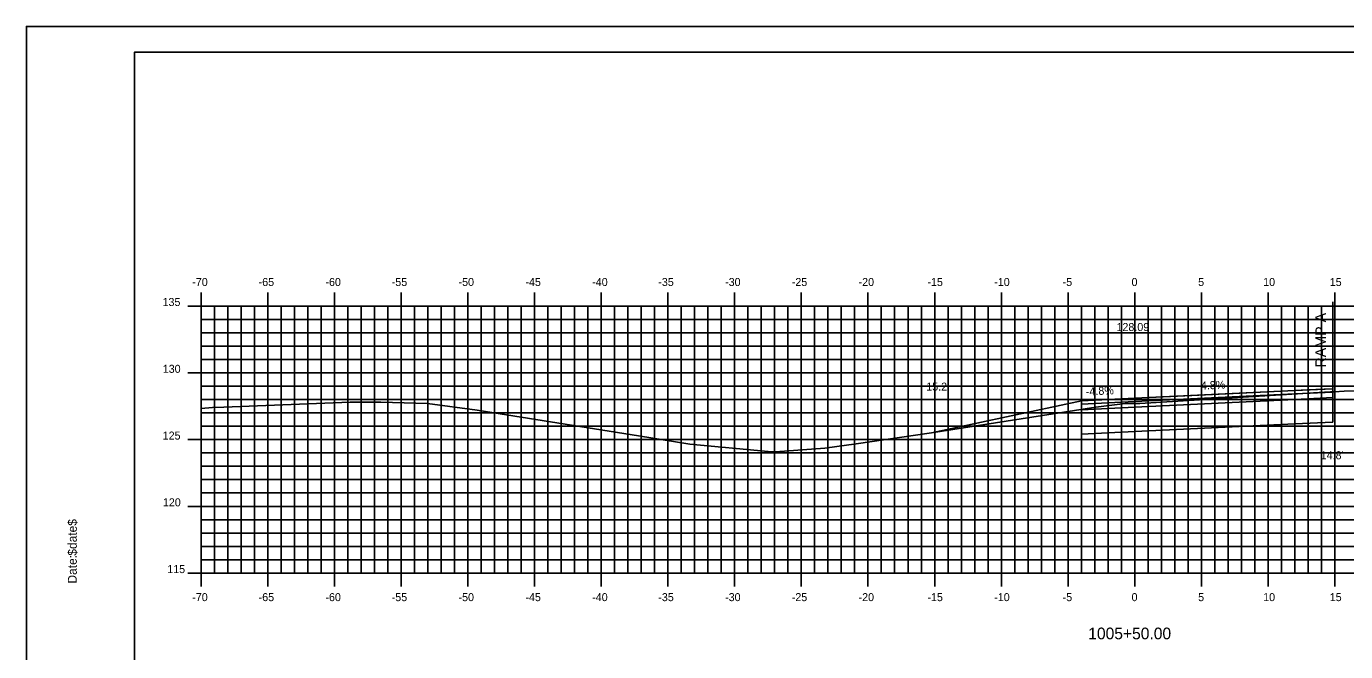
# Model space of a CAD drawing. Extents: x 851295 to 851467, y 365624 to 365734.
# Drawn here: x 851294.9 to 851393.8, y 365687.1 to 365734 of the extents above; entities that cross this region are included whole.
import ezdxf

# ---------------------------------------------------------------- set-up
doc = ezdxf.new("R2010")
doc.units = 0
for name, color, linetype in [('ANNOTATION', 7, 'Continuous'), ('BORDER', 7, 'Continuous'), ('D_Roadway_Centerline', 7, 'Continuous'), ('D_Roadway_Centerline_Text', 7, 'Continuous'), ('D_Roadway_Edge_Shoulder', 7, 'Continuous'), ('D_Roadway_Edge_TW', 7, 'Continuous'), ('D_Roadway_FinishedGrade', 7, 'Continuous'), ('D_Roadway_Pavement', 7, 'Continuous'), ('D_Roadway_SubGrade', 7, 'Continuous'), ('D_Text_Standard', 7, 'Continuous'), ('H_V ANNOTATION', 7, 'Continuous'), ('M_Roadway_Centerline', 7, 'Continuous'), ('MAJOR', 7, 'Continuous'), ('MINOR', 7, 'Continuous'), ('PLOT BOUNDARY', 7, 'Continuous'), ('S_Roadway_Centerline', 7, 'Continuous')]:
    doc.layers.add(name, color=color, linetype=linetype)

msp = doc.modelspace()

# ---------------------------------------------------------------- linework, layer by layer
at = {"layer": 'BORDER'}
msp.add_lwpolyline([(851303.009, 365627.027), (851463.009, 365627.027), (851463.009, 365732.027), (851303.009, 365732.027)], close=True, dxfattribs=at)
at = {"layer": 'D_Roadway_Centerline'}
msp.add_line((851374.009, 365705.93), (851362.77, 365703.526), dxfattribs=at)
msp.add_lwpolyline([(851374.009, 365705.93), (851374.009, 365705.93), (851376.068, 365706.029), (851378.009, 365706.122), (851378.011, 365706.122), (851382.296, 365706.328), (851390.009, 365706.698), (851390.928, 365706.742), (851392.853, 365706.835), (851392.855, 365706.835)], dxfattribs=at)
at = {"layer": 'D_Roadway_Edge_Shoulder'}
msp.add_lwpolyline([(851378.009, 365706.122), (851374.009, 365705.93), (851374.009, 365705.68), (851378.009, 365705.872)], close=True, dxfattribs=at)
at = {"layer": 'D_Roadway_Edge_TW'}
for points in [[(851390.009, 365706.698), (851392.855, 365706.835), (851392.855, 365706.585), (851390.009, 365706.448)], [(851378.009, 365706.122), (851390.009, 365706.698), (851390.009, 365706.448), (851378.009, 365705.872)]]:
    msp.add_lwpolyline(points, close=True, dxfattribs=at)
at = {"layer": 'D_Roadway_FinishedGrade'}
for p, q in [((851392.855, 365706.835), (851392.855, 365706.585)), ((851374.009, 365705.93), (851374.009, 365705.68)), ((851378.009, 365706.122), (851378.009, 365705.872)), ((851390.009, 365706.698), (851390.009, 365706.448))]:
    msp.add_line(p, q, dxfattribs=at)
at = {"layer": 'D_Roadway_Pavement'}
for points in [[(851378.009, 365705.872), (851374.009, 365705.68), (851374.009, 365705.263), (851378.009, 365705.455)], [(851378.009, 365705.872), (851390.009, 365706.448), (851390.009, 365706.031), (851378.009, 365705.455)], [(851390.009, 365706.448), (851392.855, 365706.585), (851392.855, 365706.168), (851390.009, 365706.031)]]:
    msp.add_lwpolyline(points, close=True, dxfattribs=at)
at = {"layer": 'D_Roadway_SubGrade'}
msp.add_line((851392.855, 365713.332), (851392.855, 365704.335), dxfattribs=at)
for points in [[(851378.009, 365705.455), (851374.009, 365705.263), (851374.009, 365705.763), (851374.009, 365705.93), (851374.009, 365703.43), (851378.009, 365703.622)], [(851378.009, 365705.455), (851390.009, 365706.031), (851390.009, 365704.198), (851378.009, 365703.622)], [(851390.009, 365706.031), (851392.855, 365706.168), (851392.855, 365704.335), (851390.009, 365704.198)]]:
    msp.add_lwpolyline(points, close=True, dxfattribs=at)
at = {"layer": 'MAJOR'}
for p, q in [((851308.009, 365714.029), (851308.009, 365713.027)), ((851313.009, 365714.029), (851313.009, 365713.027)), ((851318.009, 365714.029), (851318.009, 365713.027)), ((851323.009, 365714.029), (851323.009, 365713.027)), ((851328.009, 365714.029), (851328.009, 365713.027)), ((851333.009, 365714.029), (851333.009, 365713.027)), ((851338.009, 365714.029), (851338.009, 365713.027)), ((851343.009, 365714.029), (851343.009, 365713.027)), ((851348.009, 365714.029), (851348.009, 365713.027)), ((851353.009, 365714.029), (851353.009, 365713.027)), ((851358.009, 365714.029), (851358.009, 365713.027)), ((851363.009, 365714.029), (851363.009, 365713.027)), ((851368.009, 365714.029), (851368.009, 365713.027)), ((851373.009, 365714.029), (851373.009, 365713.027)), ((851378.009, 365714.029), (851378.009, 365713.027)), ((851383.009, 365714.029), (851383.009, 365713.027)), ((851388.009, 365714.029), (851388.009, 365713.027)), ((851393.009, 365714.029), (851393.009, 365713.027)), ((851307.007, 365713.027), (851308.009, 365713.027)), ((851308.009, 365713.027), (851448.009, 365713.027)), ((851308.009, 365693.027), (851308.009, 365713.027)), ((851308.009, 365693.027), (851308.009, 365713.027)), ((851308.009, 365713.027), (851448.009, 365713.027)), ((851313.009, 365693.027), (851313.009, 365713.027)), ((851318.009, 365693.027), (851318.009, 365713.027)), ((851323.009, 365693.027), (851323.009, 365713.027)), ((851328.009, 365693.027), (851328.009, 365713.027)), ((851333.009, 365693.027), (851333.009, 365713.027)), ((851338.009, 365693.027), (851338.009, 365713.027)), ((851343.009, 365693.027), (851343.009, 365713.027)), ((851348.009, 365693.027), (851348.009, 365713.027)), ((851353.009, 365693.027), (851353.009, 365713.027)), ((851358.009, 365693.027), (851358.009, 365713.027)), ((851363.009, 365693.027), (851363.009, 365713.027)), ((851368.009, 365693.027), (851368.009, 365713.027)), ((851373.009, 365693.027), (851373.009, 365713.027)), ((851378.009, 365693.027), (851378.009, 365713.027)), ((851383.009, 365693.027), (851383.009, 365713.027)), ((851388.009, 365693.027), (851388.009, 365713.027)), ((851393.009, 365693.027), (851393.009, 365713.027)), ((851307.007, 365708.027), (851308.009, 365708.027)), ((851308.009, 365708.027), (851448.009, 365708.027)), ((851307.007, 365703.027), (851308.009, 365703.027)), ((851308.009, 365703.027), (851448.009, 365703.027)), ((851307.007, 365698.027), (851308.009, 365698.027)), ((851308.009, 365698.027), (851448.009, 365698.027)), ((851307.007, 365693.027), (851308.009, 365693.027)), ((851308.009, 365693.027), (851448.009, 365693.027)), ((851308.009, 365693.027), (851448.009, 365693.027)), ((851308.009, 365692.025), (851308.009, 365693.027)), ((851313.009, 365692.025), (851313.009, 365693.027)), ((851318.009, 365692.025), (851318.009, 365693.027)), ((851323.009, 365692.025), (851323.009, 365693.027)), ((851328.009, 365692.025), (851328.009, 365693.027)), ((851333.009, 365692.025), (851333.009, 365693.027)), ((851338.009, 365692.025), (851338.009, 365693.027)), ((851343.009, 365692.025), (851343.009, 365693.027)), ((851348.009, 365692.025), (851348.009, 365693.027)), ((851353.009, 365692.025), (851353.009, 365693.027)), ((851358.009, 365692.025), (851358.009, 365693.027)), ((851363.009, 365692.025), (851363.009, 365693.027)), ((851368.009, 365692.025), (851368.009, 365693.027)), ((851373.009, 365692.025), (851373.009, 365693.027)), ((851378.009, 365692.025), (851378.009, 365693.027)), ((851383.009, 365692.025), (851383.009, 365693.027)), ((851388.009, 365692.025), (851388.009, 365693.027)), ((851393.009, 365692.025), (851393.009, 365693.027))]:
    msp.add_line(p, q, dxfattribs=at)
at = {"layer": 'MINOR'}
for p, q in [((851309.009, 365693.027), (851309.009, 365713.027)), ((851310.009, 365693.027), (851310.009, 365713.027)), ((851311.009, 365693.027), (851311.009, 365713.027)), ((851312.009, 365693.027), (851312.009, 365713.027)), ((851314.009, 365693.027), (851314.009, 365713.027)), ((851315.009, 365693.027), (851315.009, 365713.027)), ((851316.009, 365693.027), (851316.009, 365713.027)), ((851317.009, 365693.027), (851317.009, 365713.027)), ((851319.009, 365693.027), (851319.009, 365713.027)), ((851320.009, 365693.027), (851320.009, 365713.027)), ((851321.009, 365693.027), (851321.009, 365713.027)), ((851322.009, 365693.027), (851322.009, 365713.027)), ((851324.009, 365693.027), (851324.009, 365713.027)), ((851325.009, 365693.027), (851325.009, 365713.027)), ((851326.009, 365693.027), (851326.009, 365713.027)), ((851327.009, 365693.027), (851327.009, 365713.027)), ((851329.009, 365693.027), (851329.009, 365713.027)), ((851330.009, 365693.027), (851330.009, 365713.027)), ((851331.009, 365693.027), (851331.009, 365713.027)), ((851332.009, 365693.027), (851332.009, 365713.027)), ((851334.009, 365693.027), (851334.009, 365713.027)), ((851335.009, 365693.027), (851335.009, 365713.027)), ((851336.009, 365693.027), (851336.009, 365713.027)), ((851337.009, 365693.027), (851337.009, 365713.027)), ((851339.009, 365693.027), (851339.009, 365713.027)), ((851340.009, 365693.027), (851340.009, 365713.027)), ((851341.009, 365693.027), (851341.009, 365713.027)), ((851342.009, 365693.027), (851342.009, 365713.027)), ((851344.009, 365693.027), (851344.009, 365713.027)), ((851345.009, 365693.027), (851345.009, 365713.027)), ((851346.009, 365693.027), (851346.009, 365713.027)), ((851347.009, 365693.027), (851347.009, 365713.027)), ((851349.009, 365693.027), (851349.009, 365713.027)), ((851350.009, 365693.027), (851350.009, 365713.027)), ((851351.009, 365693.027), (851351.009, 365713.027)), ((851352.009, 365693.027), (851352.009, 365713.027)), ((851354.009, 365693.027), (851354.009, 365713.027)), ((851355.009, 365693.027), (851355.009, 365713.027)), ((851356.009, 365693.027), (851356.009, 365713.027)), ((851357.009, 365693.027), (851357.009, 365713.027)), ((851359.009, 365693.027), (851359.009, 365713.027)), ((851360.009, 365693.027), (851360.009, 365713.027)), ((851361.009, 365693.027), (851361.009, 365713.027)), ((851362.009, 365693.027), (851362.009, 365713.027)), ((851364.009, 365693.027), (851364.009, 365713.027)), ((851365.009, 365693.027), (851365.009, 365713.027)), ((851366.009, 365693.027), (851366.009, 365713.027)), ((851367.009, 365693.027), (851367.009, 365713.027)), ((851369.009, 365693.027), (851369.009, 365713.027)), ((851370.009, 365693.027), (851370.009, 365713.027)), ((851371.009, 365693.027), (851371.009, 365713.027)), ((851372.009, 365693.027), (851372.009, 365713.027)), ((851374.009, 365693.027), (851374.009, 365713.027)), ((851375.009, 365693.027), (851375.009, 365713.027)), ((851376.009, 365693.027), (851376.009, 365713.027)), ((851377.009, 365693.027), (851377.009, 365713.027)), ((851379.009, 365693.027), (851379.009, 365713.027)), ((851380.009, 365693.027), (851380.009, 365713.027)), ((851381.009, 365693.027), (851381.009, 365713.027)), ((851382.009, 365693.027), (851382.009, 365713.027)), ((851384.009, 365693.027), (851384.009, 365713.027)), ((851385.009, 365693.027), (851385.009, 365713.027)), ((851386.009, 365693.027), (851386.009, 365713.027)), ((851387.009, 365693.027), (851387.009, 365713.027)), ((851389.009, 365693.027), (851389.009, 365713.027)), ((851390.009, 365693.027), (851390.009, 365713.027)), ((851391.009, 365693.027), (851391.009, 365713.027)), ((851392.009, 365693.027), (851392.009, 365713.027)), ((851308.009, 365712.027), (851448.009, 365712.027)), ((851308.009, 365712.027), (851309.011, 365712.027)), ((851308.009, 365711.027), (851448.009, 365711.027)), ((851308.009, 365711.027), (851309.011, 365711.027)), ((851308.009, 365710.027), (851448.009, 365710.027)), ((851308.009, 365710.027), (851309.011, 365710.027)), ((851308.009, 365709.027), (851448.009, 365709.027)), ((851308.009, 365709.027), (851309.011, 365709.027)), ((851308.009, 365707.027), (851448.009, 365707.027)), ((851308.009, 365707.027), (851309.011, 365707.027)), ((851308.009, 365706.027), (851448.009, 365706.027)), ((851308.009, 365706.027), (851309.011, 365706.027)), ((851308.009, 365705.027), (851448.009, 365705.027)), ((851308.009, 365705.027), (851309.011, 365705.027)), ((851308.009, 365704.027), (851448.009, 365704.027)), ((851308.009, 365704.027), (851309.011, 365704.027)), ((851308.009, 365702.027), (851448.009, 365702.027)), ((851308.009, 365702.027), (851309.011, 365702.027)), ((851308.009, 365701.027), (851448.009, 365701.027)), ((851308.009, 365701.027), (851309.011, 365701.027)), ((851308.009, 365700.027), (851448.009, 365700.027)), ((851308.009, 365700.027), (851309.011, 365700.027)), ((851308.009, 365699.027), (851448.009, 365699.027)), ((851308.009, 365699.027), (851309.011, 365699.027)), ((851308.009, 365697.027), (851448.009, 365697.027)), ((851308.009, 365697.027), (851309.011, 365697.027)), ((851308.009, 365696.027), (851448.009, 365696.027)), ((851308.009, 365696.027), (851309.011, 365696.027)), ((851308.009, 365695.027), (851448.009, 365695.027)), ((851308.009, 365695.027), (851309.011, 365695.027)), ((851308.009, 365694.027), (851448.009, 365694.027)), ((851308.009, 365694.027), (851309.011, 365694.027))]:
    msp.add_line(p, q, dxfattribs=at)
at = {"layer": 'PLOT BOUNDARY'}
msp.add_lwpolyline([(851294.916, 365623.968), (851464.916, 365623.968), (851464.916, 365733.968), (851294.916, 365733.968)], close=True, dxfattribs=at)
at = {"layer": 'S_Roadway_Centerline'}
msp.add_lwpolyline([(851308.009, 365705.355), (851308.874, 365705.431), (851309.723, 365705.447), (851319.199, 365705.834), (851321.484, 365705.834), (851324.978, 365705.734), (851328.721, 365705.228), (851340.802, 365703.299), (851344.643, 365702.691), (851350.527, 365702.124), (851351.065, 365702.11), (851354.77, 365702.377), (851357.13, 365702.72), (851362.77, 365703.526), (851375.085, 365705.449), (851377.289, 365705.734), (851378.397, 365705.725), (851392.236, 365706.572), (851392.678, 365706.596), (851392.903, 365706.611), (851392.972, 365706.605), (851393.7, 365706.643), (851410.21, 365707.188)], dxfattribs=at)

# ---------------------------------------------------------------- texts
at = {"layer": 'ANNOTATION'}
for s, height, rotation, p in [('RAMP A', 0.8, 90, (851392.348, 365708.416)), ('-4.8%', 0.6, 2.74795, (851374.356, 365706.323)), ('4.8%', 0.6, 2.74806, (851382.979, 365706.761))]:
    msp.add_text(s, height=height, rotation=rotation, dxfattribs=at).set_placement(p)
at = {"layer": 'BORDER'}
for s, p in [('$date$', (851298.694, 365694.332)), ('Date:', (851298.694, 365692.244))]:
    msp.add_text(s, height=0.6696, rotation=90, dxfattribs=at).set_placement(p)
at = {"layer": 'D_Roadway_Centerline'}
for s, p in [('C', (851378.004, 365706.122)), ('L', (851378.009, 365706.114))]:
    msp.add_text(s, height=0.0146, dxfattribs=at).set_placement(p)
at = {"layer": 'D_Roadway_Centerline_Text'}
msp.add_text('128.09', height=0.6, dxfattribs=at).set_placement((851376.639, 365711.154))
at = {"layer": 'D_Text_Standard'}
for s, p in [("15.2'", (851362.379, 365706.693)), ("14.8'", (851391.948, 365701.553))]:
    msp.add_text(s, height=0.6, dxfattribs=at).set_placement(p)
at = {"layer": 'H_V ANNOTATION'}
for s, height, p in [('-70', 0.6, (851307.351, 365714.527)), ('-65', 0.6, (851312.327, 365714.527)), ('-60', 0.6, (851317.335, 365714.527)), ('-55', 0.6, (851322.305, 365714.527)), ('-50', 0.6, (851327.313, 365714.527)), ('-45', 0.6, (851332.327, 365714.527)), ('-40', 0.6, (851337.335, 365714.527)), ('-35', 0.6, (851342.289, 365714.527)), ('-30', 0.6, (851347.297, 365714.527)), ('-25', 0.6, (851352.295, 365714.527)), ('-20', 0.6, (851357.303, 365714.527)), ('-15', 0.6, (851362.466, 365714.527)), ('-10', 0.6, (851367.474, 365714.527)), ('-5', 0.6, (851372.6, 365714.527)), ('0', 0.6, (851377.768, 365714.527)), ('5', 0.6, (851382.76, 365714.527)), ('10', 0.6, (851387.634, 365714.527)), ('15', 0.6, (851392.626, 365714.527)), ('135', 0.6, (851305.123, 365713.027)), ('130', 0.6, (851305.139, 365708.027)), ('125', 0.6, (851305.134, 365703.027)), ('120', 0.6, (851305.15, 365698.027)), ('115', 0.6, (851305.476, 365693.027)), ('-70', 0.6, (851307.351, 365690.927)), ('-65', 0.6, (851312.327, 365690.927)), ('-60', 0.6, (851317.335, 365690.927)), ('-55', 0.6, (851322.305, 365690.927)), ('-50', 0.6, (851327.313, 365690.927)), ('-45', 0.6, (851332.327, 365690.927)), ('-40', 0.6, (851337.335, 365690.927)), ('-35', 0.6, (851342.289, 365690.927)), ('-30', 0.6, (851347.297, 365690.927)), ('-25', 0.6, (851352.295, 365690.927)), ('-20', 0.6, (851357.303, 365690.927)), ('-15', 0.6, (851362.466, 365690.927)), ('-10', 0.6, (851367.474, 365690.927)), ('-5', 0.6, (851372.6, 365690.927)), ('0', 0.6, (851377.768, 365690.927)), ('5', 0.6, (851382.76, 365690.927)), ('10', 0.6, (851387.634, 365690.927)), ('15', 0.6, (851392.626, 365690.927)), ('1005+50.00', 0.875, (851374.521, 365688.07))]:
    msp.add_text(s, height=height, dxfattribs=at).set_placement(p)
at = {"layer": 'M_Roadway_Centerline'}
for s, p in [('C', (851392.897, 365706.611)), ('L', (851392.903, 365706.604)), ('C', (851308.869, 365705.431)), ('L', (851308.874, 365705.424))]:
    msp.add_text(s, height=0.0146, dxfattribs=at).set_placement(p)
at = {"layer": 'MAJOR'}
msp.add_text('-', height=0.006, dxfattribs=at).set_placement((851308.005, 365693.027))

doc.saveas('drawing.dxf')
